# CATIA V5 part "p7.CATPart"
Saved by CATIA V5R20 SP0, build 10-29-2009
Part number: p7
Publications: "Line.1", "Line.2", "Line.3", "Plane.1", "Line.4", "Line.5", "Line.6", "Line.7", "Plane.2"
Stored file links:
  D:\Dropbox\IAO_2011\MMS_GR2\IAO_2011_1439_jlicbarski\p7.CATPart
  D:\Dropbox\IAO_2011\MMS_GR2\IAO_2011_1439_jlicbarski\train.CATProduct

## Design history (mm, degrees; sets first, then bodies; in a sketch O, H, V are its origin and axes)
AxisSystem1: origin (0, 0, 0), X (1, 0, 0), Y (0, 1, 0), Z (0, 0, 1)
Set1
  Point1 to Point4: linked copy from another document
Body1 (main body)
  Line1: type PtPt, FirstPoint Point1, SecondPoint Point2
  Line2: type PtPt, FirstPoint Point2, SecondPoint Point3
  Line3: type PtDir, RefPoint Point1, Direction edge [XY plane of AxisSystem1 | ZX plane of AxisSystem1], Start 0, End 22
  Plane1: type Normal, Curve Line3
  Line4: type PtDir, RefPoint Point2, Direction edge [XY plane of AxisSystem1 | ZX plane of AxisSystem1], Start 0, End 22
  Line5: type PtDir, RefPoint Point3, Direction edge [XY plane of AxisSystem1 | ZX plane of AxisSystem1], Start 0, End 22
  Line6: type PtDir, RefPoint Point4, Direction edge [XY plane of AxisSystem1 | ZX plane of AxisSystem1], Start 0, End 22
  Line7: type PtPt, FirstPoint Point2, SecondPoint Point4
  Plane2: type Normal, Curve Line4, RefPoint Point2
